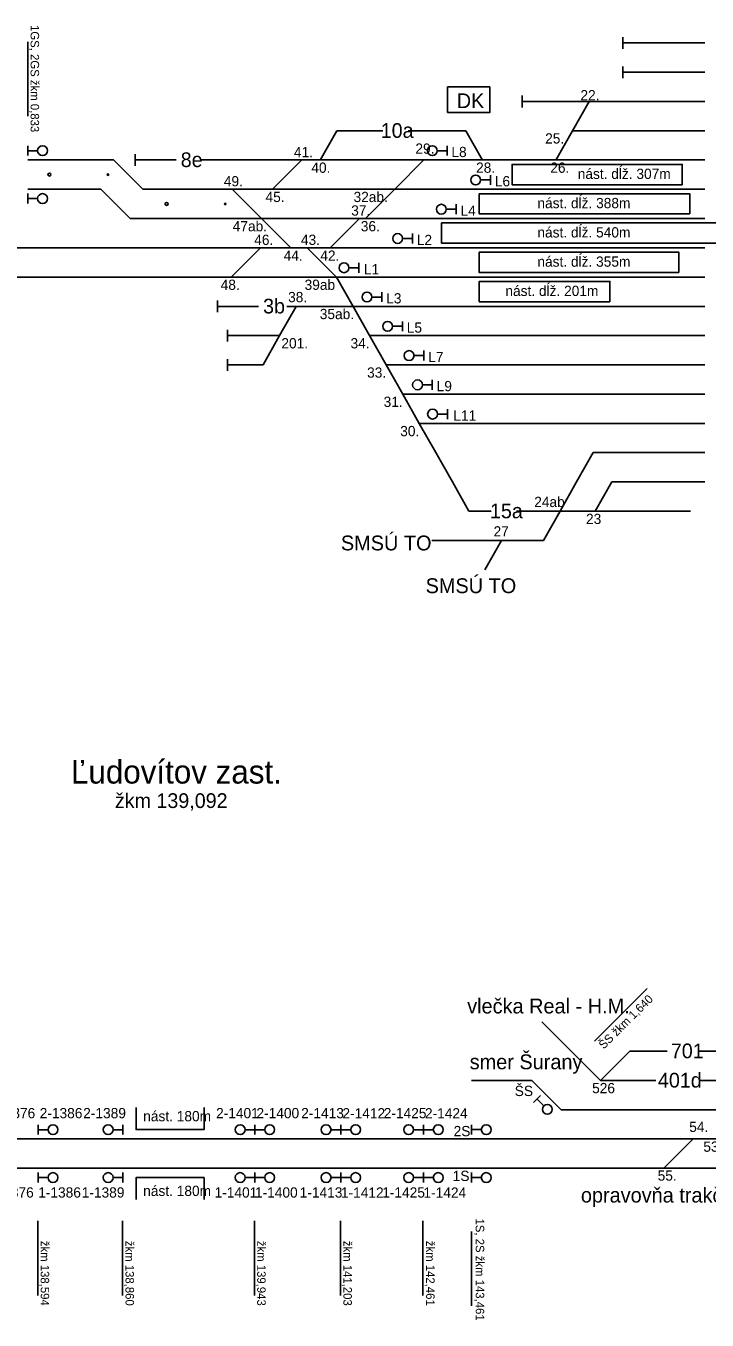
# Model space of a CAD drawing. Extents: x -119 to 851, y -238 to 59.
# Drawn here: x 390.6 to 437.1, y -119.7 to -31.3 of the extents above; entities that cross this region are included whole.
import ezdxf

# ---------------------------------------------------------------- set-up
doc = ezdxf.new("R2010")
doc.units = 0
for name, color, linetype in [('budova', 7, 'Continuous'), ('Level 2', 7, 'Continuous'), ('nastupistia', 7, 'Continuous'), ('netlač', 7, 'Continuous'), ('popisky navestidla', 7, 'Continuous'), ('popisky stanic a zastavok', 7, 'Continuous'), ('PU_navestidla', 7, 'Continuous'), ('PU_oznacenie navestidiel', 7, 'Continuous'), ('PU_stan_kolaje', 7, 'Continuous'), ('PU_vlecky', 7, 'Continuous'), ('schema_km0-1_0-2', 7, 'Continuous')]:
    doc.layers.add(name, color=color, linetype=linetype)

msp = doc.modelspace()

# ---------------------------------------------------------------- linework, layer by layer
at = {"layer": 'budova'}
msp.add_lwpolyline([(419.416, -37.213), (422.283, -37.213), (422.283, -35.465), (419.416, -35.465)], close=True, dxfattribs=at)
at = {"layer": 'Level 2'}
for p, q in [((431.381, -32.859), (431.381, -32.059)), ((431.381, -34.857), (431.381, -34.058)), ((424.497, -36.856), (424.497, -36.056)), ((398.099, -40.85), (398.099, -40.051)), ((412.985, -40.451), (417.801, -40.451)), ((418.31, -40.451), (423.557, -40.451)), ((423.557, -40.451), (436.966, -40.451)), ((388.726, -46.448), (405.794, -46.448)), ((405.794, -46.448), (421.992, -46.448)), ((421.992, -46.448), (436.966, -46.448)), ((388.726, -48.447), (420.792, -48.447)), ((420.792, -48.447), (436.966, -48.447)), ((403.719, -50.845), (403.719, -50.046)), ((404.386, -52.844), (404.386, -52.044)), ((404.386, -54.842), (404.386, -54.043)), ((438.339, -101.308), (436.556, -101.308)), ((438.339, -101.308), (436.556, -101.308)), ((436.556, -103.307), (442.248, -103.307)), ((436.556, -103.307), (442.248, -103.307)), ((429.34, -105.306), (435.739, -105.306)), ((429.34, -105.306), (435.739, -105.306)), ((421.041, -107.305), (450.209, -107.305)), ((421.041, -107.305), (450.209, -107.305))]:
    msp.add_line(p, q, dxfattribs=at)
for points in [[(398.099, -40.451), (400.892, -40.451)], [(402.616, -40.451), (412.985, -40.451)], [(417.801, -40.451), (418.31, -40.451)], [(403.719, -50.446), (406.513, -50.446)], [(408.447, -50.446), (412.985, -50.446)], [(404.386, -52.444), (407.951, -52.444)], [(404.386, -54.443), (406.822, -54.443)], [(425.163, -103.307), (421.041, -103.307)], [(425.163, -103.307), (421.041, -103.307)]]:
    msp.add_lwpolyline(points, dxfattribs=at)
at = {"layer": 'nastupistia'}
for points in [[(435.425, -42.14), (423.811, -42.14), (423.811, -40.755), (435.425, -40.755)], [(435.942, -44.138), (421.571, -44.138), (421.571, -42.753), (435.942, -42.753)], [(440.274, -46.136), (419, -46.136), (419, -44.751), (440.274, -44.751)], [(435.199, -48.135), (421.571, -48.135), (421.571, -46.75), (435.199, -46.75)], [(430.49, -50.134), (421.571, -50.134), (421.571, -48.749), (430.49, -48.749)]]:
    msp.add_lwpolyline(points, close=True, dxfattribs=at)
for points in [[(398.155, -105.167), (398.155, -106.67), (402.793, -106.67), (402.793, -105.167)], [(398.155, -105.167), (398.155, -106.67), (402.793, -106.67), (402.793, -105.167)], [(398.156, -111.444), (398.156, -109.94), (402.793, -109.94), (402.793, -111.444)], [(398.156, -111.444), (398.156, -109.94), (402.793, -109.94), (402.793, -111.444)]]:
    msp.add_lwpolyline(points, dxfattribs=at)
at = {"layer": 'netlač'}
for p, q in [((436.966, -32.459), (431.381, -32.459)), ((436.966, -34.457), (431.381, -34.457)), ((429.068, -36.456), (424.497, -36.456)), ((436.966, -36.456), (429.068, -36.456)), ((414.992, -38.454), (411.846, -38.454)), ((420.66, -38.454), (416.715, -38.454)), ((436.966, -38.454), (427.938, -38.454)), ((396.619, -40.452), (390.76, -40.452)), ((395.75, -42.451), (390.76, -42.451)), ((436.966, -42.451), (398.618, -42.451)), ((397.748, -44.449), (436.966, -44.449)), ((436.966, -50.446), (412.96, -50.446)), ((436.966, -52.444), (414.09, -52.444)), ((436.966, -54.443), (415.22, -54.443)), ((436.966, -56.441), (416.35, -56.441)), ((436.966, -58.44), (417.48, -58.44)), ((436.966, -60.438), (429.348, -60.438)), ((436.966, -62.436), (430.623, -62.436)), ((422.392, -64.435), (420.87, -64.435)), ((429.493, -64.435), (424.115, -64.435)), ((429.493, -64.435), (435.997, -64.435)), ((425.958, -66.433), (418.34, -66.433)), ((431.839, -101.308), (434.399, -101.308)), ((431.839, -101.308), (434.399, -101.308)), ((429.84, -103.307), (433.629, -103.307)), ((429.84, -103.307), (433.629, -103.307)), ((450.209, -105.306), (427.162, -105.306)), ((450.209, -105.306), (427.162, -105.306)), ((421.041, -107.305), (384.996, -107.305)), ((421.041, -109.302), (384.996, -109.302)), ((447.22, -109.302), (421.041, -109.302)), ((447.22, -109.302), (421.041, -109.302))]:
    msp.add_line(p, q, dxfattribs=at)
at = {"layer": 'popisky navestidla'}
for p, q in [((390.76, -37.467), (390.76, -32.376)), ((429.428, -100.627), (433.041, -97.04)), ((429.428, -100.627), (433.041, -97.04)), ((391.44, -112.904), (391.44, -117.995)), ((397.221, -112.904), (397.221, -117.995)), ((397.221, -112.904), (397.221, -117.995)), ((406.231, -112.904), (406.231, -117.995)), ((406.231, -112.904), (406.231, -117.995)), ((412.096, -112.904), (412.096, -117.995)), ((412.096, -112.904), (412.096, -117.995)), ((417.731, -112.904), (417.731, -117.995)), ((417.731, -112.904), (417.731, -117.995)), ((421.041, -113.616), (421.041, -118.707)), ((421.041, -113.616), (421.041, -118.707))]:
    msp.add_line(p, q, dxfattribs=at)
at = {"layer": 'PU_navestidla'}
for p, q in [((390.76, -39.478), (390.76, -40.15)), ((419.373, -39.48), (419.373, -40.152)), ((390.76, -39.816), (391.432, -39.816)), ((419.373, -39.817), (418.701, -39.817)), ((422.335, -41.479), (422.335, -42.151)), ((422.335, -41.816), (421.663, -41.816)), ((390.76, -43.423), (390.76, -42.751)), ((390.76, -43.085), (391.432, -43.085)), ((419.994, -43.815), (419.322, -43.815)), ((419.994, -43.477), (419.994, -44.149)), ((417.009, -45.814), (416.337, -45.814)), ((417.009, -45.476), (417.009, -46.148)), ((413.345, -47.475), (413.345, -48.147)), ((413.345, -47.813), (412.673, -47.813)), ((414.924, -49.474), (414.924, -50.146)), ((414.924, -49.811), (414.252, -49.811)), ((416.329, -51.81), (415.657, -51.81)), ((416.329, -51.472), (416.329, -52.144)), ((417.793, -53.808), (417.121, -53.808)), ((417.793, -53.471), (417.793, -54.143)), ((418.368, -55.469), (418.368, -56.141)), ((418.368, -55.806), (417.696, -55.806)), ((419.394, -57.805), (418.722, -57.805)), ((419.394, -57.468), (419.394, -58.14)), ((425.265, -104.805), (425.742, -104.331)), ((425.265, -104.805), (425.742, -104.331)), ((425.504, -104.567), (425.978, -105.044)), ((425.504, -104.567), (425.978, -105.044)), ((391.474, -106.333), (391.474, -107.005)), ((391.474, -106.671), (392.146, -106.671)), ((397.255, -106.671), (396.583, -106.671)), ((397.255, -106.671), (396.583, -106.671)), ((397.255, -106.333), (397.255, -107.005)), ((397.255, -106.333), (397.255, -107.005)), ((406.265, -106.671), (405.593, -106.671)), ((406.265, -106.671), (405.593, -106.671)), ((406.265, -106.333), (406.265, -107.005)), ((406.265, -106.333), (406.265, -107.005)), ((406.265, -106.333), (406.265, -107.005)), ((406.265, -106.333), (406.265, -107.005)), ((406.265, -106.671), (406.937, -106.671)), ((406.265, -106.671), (406.937, -106.671)), ((412.13, -106.671), (411.458, -106.671)), ((412.13, -106.671), (411.458, -106.671)), ((412.13, -106.333), (412.13, -107.005)), ((412.13, -106.333), (412.13, -107.005)), ((412.13, -106.333), (412.13, -107.005)), ((412.13, -106.333), (412.13, -107.005)), ((412.13, -106.671), (412.802, -106.671)), ((412.13, -106.671), (412.802, -106.671)), ((417.764, -106.671), (417.092, -106.671)), ((417.764, -106.671), (417.092, -106.671)), ((417.764, -106.333), (417.764, -107.005)), ((417.764, -106.333), (417.764, -107.005)), ((417.764, -106.333), (417.764, -107.005)), ((417.764, -106.333), (417.764, -107.005)), ((417.764, -106.671), (418.436, -106.671)), ((417.764, -106.671), (418.436, -106.671)), ((421.041, -106.331), (421.041, -107.003)), ((421.041, -106.331), (421.041, -107.003)), ((421.041, -106.669), (421.713, -106.669)), ((421.041, -106.669), (421.713, -106.669)), ((391.474, -110.276), (391.474, -109.604)), ((391.474, -109.939), (392.146, -109.939)), ((397.255, -109.939), (396.583, -109.939)), ((397.255, -109.939), (396.583, -109.939)), ((397.255, -110.276), (397.255, -109.604)), ((397.255, -110.276), (397.255, -109.604)), ((406.265, -109.939), (405.593, -109.939)), ((406.265, -109.939), (405.593, -109.939)), ((406.265, -110.276), (406.265, -109.604)), ((406.265, -110.276), (406.265, -109.604)), ((406.265, -110.276), (406.265, -109.604)), ((406.265, -110.276), (406.265, -109.604)), ((406.265, -109.939), (406.937, -109.939)), ((406.265, -109.939), (406.937, -109.939)), ((412.13, -109.939), (411.458, -109.939)), ((412.13, -109.939), (411.458, -109.939)), ((412.13, -110.276), (412.13, -109.604)), ((412.13, -110.276), (412.13, -109.604)), ((412.13, -110.276), (412.13, -109.604)), ((412.13, -110.276), (412.13, -109.604)), ((412.13, -109.939), (412.802, -109.939)), ((412.13, -109.939), (412.802, -109.939)), ((417.764, -109.939), (417.092, -109.939)), ((417.764, -109.939), (417.092, -109.939)), ((417.764, -110.276), (417.764, -109.604)), ((417.764, -110.276), (417.764, -109.604)), ((417.764, -110.276), (417.764, -109.604)), ((417.764, -110.276), (417.764, -109.604)), ((417.764, -109.939), (418.436, -109.939)), ((417.764, -109.939), (418.436, -109.939)), ((421.041, -110.276), (421.041, -109.604)), ((421.041, -110.276), (421.041, -109.604)), ((421.041, -109.938), (421.713, -109.938)), ((421.041, -109.938), (421.713, -109.938))]:
    msp.add_line(p, q, dxfattribs=at)
for centre in [(391.768, -39.814), (418.365, -39.816), (421.327, -41.815), (391.768, -43.087), (418.986, -43.813), (416.001, -45.812), (412.337, -47.811), (413.916, -49.81), (415.321, -51.808), (416.785, -53.807), (417.36, -55.805), (418.386, -57.804), (426.214, -105.283), (426.214, -105.283), (392.482, -106.669), (396.247, -106.669), (396.247, -106.669), (405.257, -106.669), (405.257, -106.669), (407.273, -106.669), (407.273, -106.669), (411.122, -106.669), (411.122, -106.669), (413.138, -106.669), (413.138, -106.669), (416.756, -106.669), (416.756, -106.669), (418.772, -106.669), (418.772, -106.669), (422.049, -106.667), (422.049, -106.667), (392.482, -109.94), (396.247, -109.94), (396.247, -109.94), (405.257, -109.94), (405.257, -109.94), (407.273, -109.94), (407.273, -109.94), (411.122, -109.94), (411.122, -109.94), (413.138, -109.94), (413.138, -109.94), (416.756, -109.94), (416.756, -109.94), (418.772, -109.94), (418.772, -109.94), (422.049, -109.94), (422.049, -109.94)]:
    msp.add_circle(centre, 0.336, dxfattribs=at)
at = {"layer": 'PU_stan_kolaje'}
msp.add_line((425.163, -103.307), (425.163, -103.307), dxfattribs=at)
msp.add_line((425.163, -103.307), (425.163, -103.307), dxfattribs=at)
for points in [[(427.938, -38.454), (429.068, -36.456)], [(410.716, -40.453), (411.846, -38.454)], [(420.66, -38.454), (421.79, -40.453)], [(426.808, -40.453), (427.938, -38.454)], [(396.619, -40.452), (398.618, -42.451)], [(409.465, -40.451), (407.466, -42.45)], [(417.801, -40.451), (415.802, -42.45)], [(395.75, -42.451), (397.749, -44.45)], [(404.706, -42.45), (406.705, -44.449)], [(415.802, -42.45), (413.803, -44.449)], [(406.705, -44.449), (408.704, -46.448)], [(413.397, -44.448), (411.398, -46.447)], [(406.644, -46.448), (404.645, -48.447)], [(409.831, -46.448), (411.83, -48.447)], [(412.96, -50.446), (411.83, -48.447)], [(407.951, -52.444), (409.081, -50.446)], [(414.09, -52.444), (412.96, -50.446)], [(406.822, -54.443), (407.951, -52.444)], [(415.22, -54.443), (414.09, -52.444)], [(416.35, -56.441), (415.22, -54.443)], [(417.48, -58.44), (416.35, -56.441)], [(418.61, -60.438), (417.48, -58.44)], [(419.74, -62.436), (418.61, -60.438)], [(428.218, -62.436), (429.348, -60.438)], [(420.87, -64.435), (419.74, -62.436)], [(427.088, -64.435), (428.218, -62.436)], [(429.493, -64.435), (430.623, -62.436)], [(425.958, -66.433), (427.088, -64.435)], [(421.957, -68.432), (423.086, -66.433)], [(425.842, -99.309), (427.841, -101.308)], [(425.842, -99.309), (427.841, -101.308)], [(427.841, -101.308), (429.84, -103.307)], [(427.841, -101.308), (429.84, -103.307)], [(431.839, -101.308), (429.84, -103.307)], [(431.839, -101.308), (429.84, -103.307)], [(425.163, -103.307), (427.162, -105.306)], [(425.163, -103.307), (427.162, -105.306)], [(436.161, -107.305), (434.186, -109.28)], [(436.161, -107.305), (434.186, -109.28)]]:
    msp.add_lwpolyline(points, dxfattribs=at)
at = {"layer": 'schema_km0-1_0-2'}
for centre, radius in [((392.239, -41.45), 0.1), ((396.238, -41.45), 0.0502), ((400.238, -43.45), 0.1), ((404.237, -43.45), 0.0502)]:
    msp.add_circle(centre, radius, dxfattribs=at)

# ---------------------------------------------------------------- texts
at = {"layer": 'budova'}
msp.add_text('DK', height=1.0044, dxfattribs=at).set_placement((420.045, -36.909))
at = {"layer": 'nastupistia'}
for s, p in [('nást. dĺž. 307m', (428.291, -41.746)), ('nást. dĺž. 388m', (425.54, -43.743)), ('nást. dĺž. 540m', (425.54, -45.742)), ('nást. dĺž. 355m', (425.54, -47.741)), ('nást. dĺž. 201m', (423.355, -49.74)), ('nást. 180m', (398.639, -106.098)), ('nást. 180m', (398.639, -106.098)), ('nást. 180m', (398.639, -111.2)), ('nást. 180m', (398.639, -111.2))]:
    msp.add_text(s, height=0.7, dxfattribs=at).set_placement(p)
at = {"layer": 'popisky navestidla'}
for s, rotation, p in [('1GS, 2GS žkm 0,833', 270, (390.954, -31.235)), ('ŠS žkm 1,640', 44.80302, (430.062, -101.21)), ('ŠS žkm 1,640', 44.80302, (430.062, -101.21)), ('1S, 2S žkm 143,461', 270, (421.33, -112.738)), ('1S, 2S žkm 143,461', 270, (421.33, -112.738)), ('žkm 138,594', 270, (391.642, -114.261)), ('žkm 138,860', 270, (397.43, -114.261)), ('žkm 138,860', 270, (397.43, -114.261)), ('žkm 139,943', 270, (406.417, -114.261)), ('žkm 139,943', 270, (406.417, -114.261)), ('žkm 141,203', 270, (412.3, -114.261)), ('žkm 141,203', 270, (412.3, -114.261)), ('žkm 142,461', 270, (417.948, -114.261)), ('žkm 142,461', 270, (417.948, -114.261))]:
    msp.add_text(s, height=0.57931, rotation=rotation, dxfattribs=at).set_placement(p)
at = {"layer": 'popisky stanic a zastavok'}
for s, height, p in [('Ľudovítov zast.', 1.6, (393.71, -83.035)), ('Ľudovítov zast.', 1.6, (393.71, -83.035)), ('žkm 139,092', 1.00438, (396.706, -84.704)), ('žkm 139,092', 1.00438, (396.706, -84.704))]:
    msp.add_text(s, height=height, dxfattribs=at).set_placement(p)
at = {"layer": 'PU_oznacenie navestidiel'}
for s, p in [('22.', (428.476, -36.38)), ('25.', (426.068, -39.328)), ('41.', (408.924, -40.265)), ('29.', (417.214, -40.024)), ('L8', (419.671, -40.254)), ('40.', (410.113, -41.325)), ('28.', (421.356, -41.325)), ('26.', (426.42, -41.325)), ('49.', (404.142, -42.253)), ('L6', (422.634, -42.253)), ('45.', (406.986, -43.324)), ('32ab.', (412.994, -43.326)), ('37.', (412.833, -44.251)), ('L4', (420.293, -44.263)), ('47ab.', (404.747, -45.324)), ('36.', (413.488, -45.324)), ('46.', (406.216, -46.25)), ('43.', (409.403, -46.25)), ('L2', (417.31, -46.262)), ('44.', (408.224, -47.334)), ('42.', (410.724, -47.334)), ('L1', (413.699, -48.261)), ('39ab', (409.653, -49.321)), ('48.', (403.927, -49.321)), ('38.', (408.529, -50.162)), ('L3', (415.222, -50.248)), ('35ab.', (410.689, -51.32)), ('L5', (416.625, -52.246)), ('201.', (408.068, -53.318)), ('34.', (412.789, -53.318)), ('L7', (418.092, -54.257)), ('33.', (413.919, -55.317)), ('L9', (418.665, -56.243)), ('31.', (415.048, -57.315)), ('L11', (419.805, -58.254)), ('30.', (416.178, -59.314)), ('24ab', (425.323, -64.153)), ('23', (428.858, -65.309)), ('27', (422.546, -66.163)), ('ŠS', (423.992, -104.375)), ('ŠS', (423.992, -104.375)), ('526', (429.274, -104.182)), ('526', (429.274, -104.182)), ('2-1376', (388.356, -105.891)), ('2-1386', (391.576, -105.891)), ('2-1389', (394.546, -105.891)), ('2-1389', (394.546, -105.891)), ('2-1401', (403.613, -105.891)), ('2-1401', (403.613, -105.891)), ('2-1400', (406.368, -105.891)), ('2-1400', (406.368, -105.891)), ('2-1413', (409.422, -105.891)), ('2-1413', (409.422, -105.891)), ('2-1412', (412.234, -105.903)), ('2-1412', (412.234, -105.903)), ('2-1425', (415.054, -105.891)), ('2-1425', (415.054, -105.891)), ('2-1424', (417.867, -105.903)), ('2-1424', (417.867, -105.903)), ('2S', (419.824, -107.117)), ('2S', (419.824, -107.117)), ('54.', (435.902, -106.829)), ('54.', (435.902, -106.829)), ('53.', (436.864, -108.18)), ('53.', (436.864, -108.18)), ('1S', (419.761, -110.178)), ('1S', (419.761, -110.178)), ('55.', (433.747, -110.154)), ('55.', (433.747, -110.154)), ('1-1376', (388.254, -111.308)), ('1-1386', (391.474, -111.308)), ('1-1389', (394.444, -111.308)), ('1-1389', (394.444, -111.308)), ('1-1401', (403.511, -111.308)), ('1-1401', (403.511, -111.308)), ('1-1400', (406.266, -111.308)), ('1-1400', (406.266, -111.308)), ('1-1413', (409.32, -111.308)), ('1-1413', (409.32, -111.308)), ('1-1412', (412.132, -111.32)), ('1-1412', (412.132, -111.32)), ('1-1425', (414.952, -111.308)), ('1-1425', (414.952, -111.308)), ('1-1424', (417.765, -111.32)), ('1-1424', (417.765, -111.32))]:
    msp.add_text(s, height=0.7, dxfattribs=at).set_placement(p)
at = {"layer": 'PU_stan_kolaje'}
for s, p in [('10a', (414.847, -38.939)), ('8e', (401.2, -40.936)), ('3b', (406.82, -50.931)), ('15a', (422.303, -64.92)), ('701', (434.648, -101.793)), ('701', (434.648, -101.793)), ('401d', (433.767, -103.793)), ('401d', (433.767, -103.793))]:
    msp.add_text(s, height=1.0044, dxfattribs=at).set_placement(p)
at = {"layer": 'PU_vlecky'}
for s, p in [('SMSÚ TO', (412.13, -67.113)), ('SMSÚ TO', (417.912, -70.033)), ('vlečka Real - H.M.', (420.75, -98.735)), ('vlečka Real - H.M.', (420.75, -98.735)), ('smer Šurany', (420.92, -102.546)), ('smer Šurany', (420.92, -102.546)), ('opravovňa trakčného vedenia', (428.508, -111.646)), ('opravovňa trakčného vedenia', (428.508, -111.646))]:
    msp.add_text(s, height=1.015, dxfattribs=at).set_placement(p)

doc.saveas('drawing.dxf')
